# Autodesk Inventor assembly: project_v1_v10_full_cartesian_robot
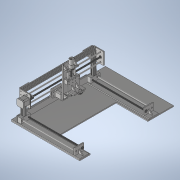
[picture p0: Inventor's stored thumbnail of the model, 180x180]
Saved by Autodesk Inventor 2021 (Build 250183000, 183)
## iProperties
Created: 2026-10
Part Number: project_v1_v10_full_cartesian_robot
Description: STEP AP203
Document SubType Name: Assembly
Designer: hp
Title: project_v1_v10_full_cartesian_robot.step
Sending System: Autodesk Translation Framework v15.15.0.0
Preprocessor: ST-DEVELOPER v20.2
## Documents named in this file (19)
- C:\Users\hp\Downloads\project_v1_v10_full_cartesian_robot.iam
- C:\Users\hp\Downloads\back_plate.ipt
- C:\Users\hp\Downloads\rip.ipt
- C:\Users\hp\Downloads\end_support.ipt
- C:\Users\hp\Downloads\8mm_Bar.ipt
- C:\Users\hp\Downloads\block_Nut_assembly.iam
- C:\Users\hp\Downloads\block_Nut_assembly_1.iam
- C:\Users\hp\Downloads\Lead Screw T8X8X500.ipt
- C:\Users\hp\Downloads\688_bearing.ipt
- C:\Users\hp\Downloads\left_right_Legs.ipt
- C:\Users\hp\Downloads\Small_Z_Beadge_Assembly.iam
- C:\Users\hp\Downloads\GT2 Timing Pulley 20 Tooth_8mm.ipt
- C:\Users\hp\Downloads\Low Profile Screw M5_M5 x 25.ipt
- C:\Users\hp\Downloads\Nylon Insert Lock Nut M5.ipt
- C:\Users\hp\Downloads\GT2 Timing idelar 20 Tooth.ipt
- C:\Users\hp\Downloads\Gt2_930.ipt
- C:\Users\hp\Downloads\nema17_Assembly.iam
- C:\Users\hp\Downloads\Double Tee Nut.ipt
- C:\Users\hp\Downloads\project_Base.ipt
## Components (34 placed, 17 different names)
1. back_plate:1
2. rip:7
3. end_support:2
4. rip:8
5. 8mm_Bar:1
6. 8mm_Bar:2
7. block_Nut_assembly:1 [sub-assembly]
8. block_Nut_assembly:2 [sub-assembly]
9. Lead Screw T8X8X500:1
10. Lead Screw T8X8X500:2
11. 688_bearing:5
12. left_right_Legs:1
13. left_right_Legs:2
14. Small_Z_Beadge_Assembly:1 [sub-assembly]
15. GT2 Timing Pulley 20 Tooth_8mm:1
16. GT2 Timing Pulley 20 Tooth_8mm:2
17. Low Profile Screw M5_M5 x 25:1
18. Low Profile Screw M5_M5 x 25:2
19. Nylon Insert Lock Nut M5:1
20. Nylon Insert Lock Nut M5:2
21. GT2 Timing idelar 20 Tooth:1
22. GT2 Timing idelar 20 Tooth:2
23. Nylon Insert Lock Nut M5:3
24. Nylon Insert Lock Nut M5:4
25. Gt2_930:1
26. nema17_Assembly:1 [sub-assembly]
27. Double Tee Nut:1
28. Double Tee Nut:2
29. project_Base:1
30. 688_bearing:7
31. 688_bearing:8
32. rip:11
33. rip:12
34. end_support:3
